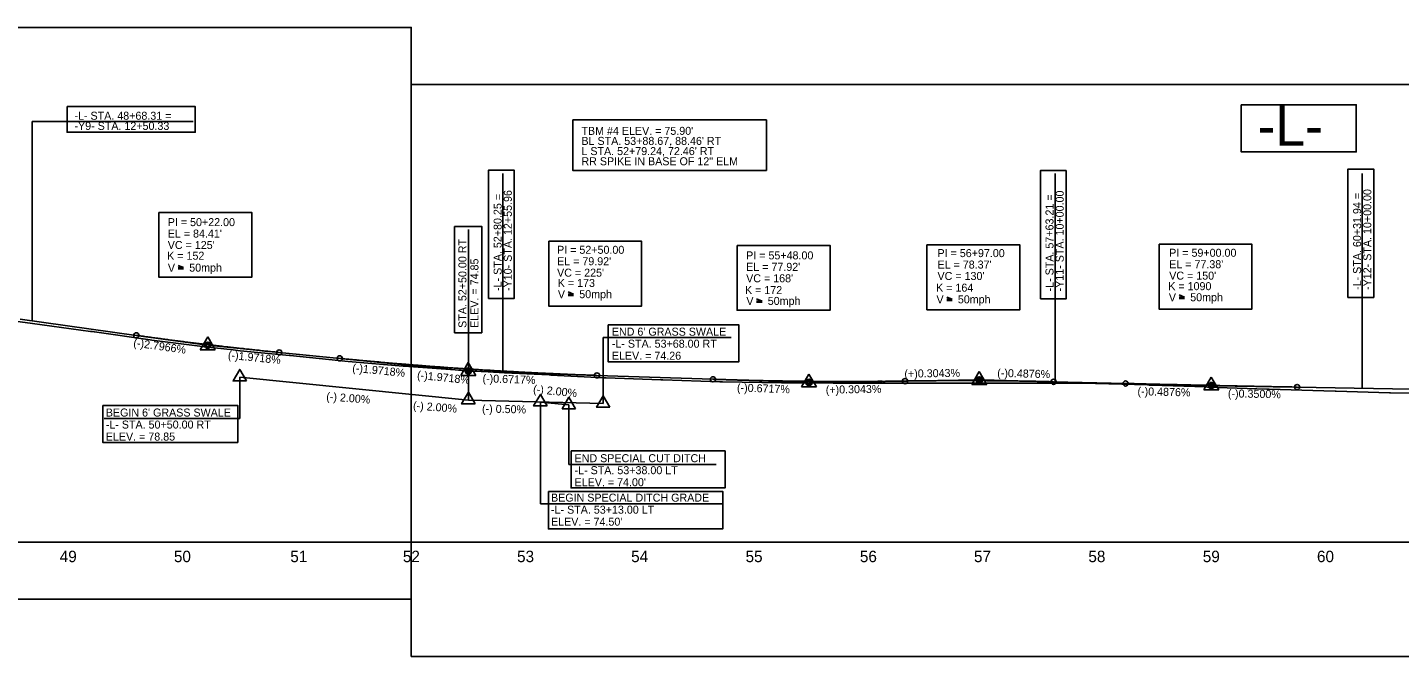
# Model space of a CAD drawing. Extents: x 2366464 to 2375718, y 801842 to 804354.
# Drawn here: x 2371182 to 2372383, y 803754 to 804304 of the extents above; entities that cross this region are included whole.
import ezdxf

# ---------------------------------------------------------------- set-up
doc = ezdxf.new("R2010")
doc.units = 0
for name, color, linetype in [('Exist Profile Cell', 7, 'Continuous'), ('Exist Vertical Profile Ground Line', 7, 'Continuous'), ('Exist Vertical Profile Horizontal Axis Label Major', 7, 'Continuous'), ('Prop Grid Mask', 7, 'Continuous'), ('Prop PFL VPI Symbol CELL', 7, 'Continuous'), ('Prop Vertical Profile Curve Label', 7, 'Continuous'), ('Prop Vertical Profile Ditch Grade Left', 7, 'Continuous'), ('Prop Vertical Profile Ditch Grade Left Label', 7, 'Continuous'), ('Prop Vertical Profile Ditch Grade Right', 7, 'Continuous'), ('Prop Vertical Profile Ditch Grade Right Label', 7, 'Continuous'), ('Prop Vertical Profile Grade', 7, 'Continuous'), ('Prop Vertical Profile Grade Label', 7, 'Continuous'), ('Prop VPI Label', 7, 'Continuous'), ('Scratch_Level_5', 7, 'Continuous'), ('Sheet Layout Profile Border Port 1', 7, 'Continuous'), ('Sheet Layout Profile Border Port 2', 7, 'Continuous')]:
    doc.layers.add(name, color=color, linetype=linetype)

# ---------------------------------------------------------------- blocks, each defined once
blk = doc.blocks.new('Profile VPI Symbol')
at = {"layer": 'Prop PFL VPI Symbol CELL'}
for p, q in [((-0.001, 0.147), (-0.13, -0.077)), ((-0.001, 0.147), (0.129, -0.077)), ((-0.13, -0.077), (0.129, -0.077))]:
    blk.add_line(p, q, dxfattribs=at)
for radius in [0.035, 0.024]:
    blk.add_circle((-0.001, -0.003), radius, dxfattribs=at)

msp = doc.modelspace()

# ---------------------------------------------------------------- linework, layer by layer
at = {"layer": 'Exist Profile Cell'}
msp.add_line((2367318, 803854), (2374481.8, 803854), dxfattribs=at)
at = {"layer": 'Exist Vertical Profile Ground Line'}
for points in [[(2371156.1, 804049.1), (2371186.8, 804045.1)], [(2371186.8, 804045.1), (2371237.4, 804038.3), (2371239.2, 804038.1), (2371240.9, 804037.8), (2371289.5, 804030.8), (2371291.1, 804030.6), (2371340.1, 804024.6), (2371340.4, 804024.5), (2371362.1, 804022), (2371368.4, 804021.4), (2371411.6, 804017.2), (2371412, 804017.2), (2371462.9, 804012), (2371511, 804007.8), (2371511.9, 804007.8), (2371560.5, 804004.3), (2371561, 804004.3), (2371599.7, 804001.9), (2371638.6, 804000.2), (2371640, 804000.1), (2371686.8, 803997.7), (2371688.6, 803997.7), (2371736.4, 803995.8), (2371738.1, 803995.8), (2371788, 803994.2), (2371789.1, 803994.2), (2371790.2, 803994.2), (2371842, 803993.3), (2371887, 803992.9), (2371887.5, 803992.9), (2371888, 803992.9), (2371914.4, 803992.9), (2371922.5, 803992.9), (2371930.6, 803992.9), (2371935.2, 803992.9), (2371935.7, 803992.9), (2371938.6, 803992.9), (2371946.7, 803992.9), (2371954.8, 803993), (2371962.8, 803993), (2371970.9, 803993), (2371979, 803993), (2371981.1, 803993), (2371987.8, 803993), (2371996.6, 803993), (2372005.4, 803993), (2372014.2, 803993), (2372023, 803993), (2372027.2, 803993), (2372028.8, 803993), (2372031.9, 803993), (2372040.7, 803993), (2372079.6, 803993), (2372080.2, 803993), (2372080.7, 803993), (2372116.5, 803992.8), (2372117, 803992.7), (2372162.2, 803991.4), (2372163.7, 803991.3), (2372165.4, 803991.3), (2372213.1, 803989.7), (2372214.7, 803989.6), (2372266.6, 803987.8), (2372268.5, 803987.8), (2372316.3, 803986.3), (2372326.4, 803986), (2372327.1, 803985.9), (2372373.9, 803984.6), (2372374.8, 803984.6), (2372426.7, 803983.6)]]:
    msp.add_lwpolyline(points, dxfattribs=at)
at = {"layer": 'Prop Grid Mask'}
for points in [[(2371216.9, 804234.8), (2371329, 804234.8), (2371329, 804212.3), (2371216.9, 804212.3)], [(2372244.1, 804236.4), (2372344.8, 804236.4), (2372344.8, 804195.1), (2372244.1, 804195.1)], [(2371659.3, 804223.2), (2371828.8, 804223.2), (2371828.8, 804179), (2371659.3, 804179)], [(2371585.6, 804067.1), (2371585.6, 804179.2), (2371608.1, 804179.2), (2371608.1, 804067.1)], [(2372068.4, 804066.7), (2372068.4, 804178.8), (2372090.9, 804178.8), (2372090.9, 804066.7)], [(2372337.4, 804068), (2372337.4, 804180.1), (2372360, 804180.1), (2372360, 804068)], [(2371297.2, 804142.3), (2371378.5, 804142.3), (2371378.5, 804085.6), (2371297.2, 804085.6)], [(2371556, 804130.1), (2371579.7, 804130.1), (2371579.7, 804037.1), (2371556, 804037.1)], [(2371638.3, 804117.1), (2371719.6, 804117.1), (2371719.6, 804060.4), (2371638.3, 804060.4)], [(2371803.1, 804113.4), (2371884.4, 804113.4), (2371884.4, 804056.7), (2371803.1, 804056.7)], [(2371969.2, 804113.9), (2372050.5, 804113.9), (2372050.5, 804057.2), (2371969.2, 804057.2)], [(2372172.2, 804114.5), (2372253.5, 804114.5), (2372253.5, 804057.8), (2372172.2, 804057.8)], [(2371690.2, 804043.9), (2371804.7, 804043.9), (2371804.7, 804011.7), (2371690.2, 804011.7)], [(2371248.2, 803973.5), (2371366.3, 803973.5), (2371366.3, 803941.2), (2371248.2, 803941.2)], [(2371657.8, 803933.8), (2371792.6, 803933.8), (2371792.6, 803901.4), (2371657.8, 803901.4)], [(2371638, 803898.3), (2371790.5, 803898.3), (2371790.5, 803865.5), (2371638, 803865.5)]]:
    msp.add_lwpolyline(points, close=True, dxfattribs=at)
at = {"layer": 'Prop Vertical Profile Curve Label'}
for p, q in [((2371314, 804094), (2371318.8, 804094)), ((2371314, 804092.9), (2371318.8, 804092.9)), ((2371318.8, 804094), (2371314.1, 804096)), ((2371655.3, 804070.7), (2371660, 804070.7)), ((2371655.3, 804069.7), (2371660, 804069.7)), ((2371660, 804070.7), (2371655.4, 804072.7)), ((2371820.1, 804064.8), (2371824.9, 804064.8)), ((2371820.1, 804063.8), (2371824.9, 804063.8)), ((2371824.9, 804064.8), (2371820.2, 804066.8)), ((2371986.5, 804066.3), (2371991.2, 804066.3)), ((2371986.5, 804065.2), (2371991.2, 804065.2)), ((2371991.2, 804066.3), (2371986.6, 804068.3)), ((2372189.7, 804068.1), (2372194.5, 804068.1)), ((2372189.7, 804067), (2372194.5, 804067)), ((2372194.5, 804068.1), (2372189.8, 804070.1))]:
    msp.add_line(p, q, dxfattribs=at)
for centre in [(2371277.5, 804034.8), (2371402.5, 804019.9), (2371455.5, 804014.7), (2371680.5, 803999.8), (2371782, 803996.4), (2371950, 803994.8), (2371950, 803994.8), (2372080, 803994.2), (2372143, 803992.7), (2372293, 803989.6)]:
    msp.add_circle(centre, 2.25, dxfattribs=at)
at = {"layer": 'Prop Vertical Profile Ditch Grade Left'}
msp.add_line((2371631, 803976.5), (2371656, 803974), dxfattribs=at)
at = {"layer": 'Prop Vertical Profile Ditch Grade Left Label'}
for p, q in [((2371631, 803887.5), (2371631, 803976.5)), ((2371656, 803922), (2371656, 803974)), ((2371784.8, 803922), (2371656, 803922)), ((2371789.8, 803887.5), (2371631, 803887.5))]:
    msp.add_line(p, q, dxfattribs=at)
for points in [[(2371636.8, 803973.1), (2371631, 803983.2), (2371625.1, 803973.1)], [(2371661.8, 803970.6), (2371656, 803980.7), (2371650.1, 803970.6)]]:
    msp.add_lwpolyline(points, close=True, dxfattribs=at)
at = {"layer": 'Prop Vertical Profile Ditch Grade Right'}
for p, q in [((2371368, 803998.2), (2371568, 803978.2)), ((2371568, 803978.2), (2371686, 803975.3))]:
    msp.add_line(p, q, dxfattribs=at)
at = {"layer": 'Prop Vertical Profile Ditch Grade Right Label'}
for p, q in [((2371568, 804127.2), (2371568, 804035.9)), ((2371568, 804035.9), (2371568, 803978.2)), ((2371686, 804032.9), (2371686, 803975.3)), ((2371797.8, 804032.9), (2371686, 804032.9)), ((2371368, 803962), (2371368, 803998.2)), ((2371368, 803962), (2371249.5, 803962))]:
    msp.add_line(p, q, dxfattribs=at)
for points in [[(2371373.8, 803994.9), (2371368, 804005), (2371362.1, 803994.9)], [(2371573.8, 803974.9), (2371568, 803985), (2371562.1, 803974.9)], [(2371691.8, 803971.9), (2371686, 803982), (2371680.1, 803971.9)]]:
    msp.add_lwpolyline(points, close=True, dxfattribs=at)
at = {"layer": 'Prop Vertical Profile Grade'}
for p, q in [((2371176, 804049), (2371277.5, 804034.8)), ((2371402.5, 804019.9), (2371455.5, 804014.7)), ((2371680.5, 803999.8), (2371782, 803996.4)), ((2372080, 803994.2), (2372143, 803992.7)), ((2372293, 803989.6), (2372808, 803980.6))]:
    msp.add_line(p, q, dxfattribs=at)
for points in [[(2371277.5, 804034.8), (2371280, 804034.4), (2371282.5, 804034.1), (2371285, 804033.8), (2371287.5, 804033.4), (2371290, 804033.1), (2371292.5, 804032.7), (2371295, 804032.4), (2371297.5, 804032.1), (2371300, 804031.7), (2371302.5, 804031.4), (2371305, 804031.1), (2371307.5, 804030.7), (2371310, 804030.4), (2371312.5, 804030.1), (2371315, 804029.8), (2371317.5, 804029.5), (2371320, 804029.1), (2371322.5, 804028.8), (2371325, 804028.5), (2371327.5, 804028.2), (2371330, 804027.9), (2371332.5, 804027.6), (2371335, 804027.3), (2371337.5, 804027), (2371340, 804026.7), (2371342.5, 804026.4), (2371345, 804026.1), (2371347.5, 804025.8), (2371350, 804025.5), (2371352.5, 804025.2), (2371355, 804024.9), (2371357.5, 804024.7), (2371360, 804024.4), (2371362.5, 804024.1), (2371365, 804023.8), (2371367.5, 804023.5), (2371370, 804023.3), (2371372.5, 804023), (2371375, 804022.7), (2371377.5, 804022.5), (2371380, 804022.2), (2371382.5, 804021.9), (2371385, 804021.7), (2371387.5, 804021.4), (2371390, 804021.1), (2371392.5, 804020.9), (2371395, 804020.6), (2371397.5, 804020.4), (2371400, 804020.1), (2371402.5, 804019.9)], [(2371455.5, 804014.7), (2371460, 804014.2), (2371464.5, 804013.8), (2371469, 804013.4), (2371473.5, 804012.9), (2371478, 804012.5), (2371482.5, 804012.1), (2371487, 804011.7), (2371491.5, 804011.3), (2371496, 804010.9), (2371500.5, 804010.5), (2371505, 804010.1), (2371509.5, 804009.8), (2371514, 804009.4), (2371518.5, 804009), (2371523, 804008.7), (2371527.5, 804008.3), (2371532, 804008), (2371536.5, 804007.6), (2371541, 804007.3), (2371545.5, 804007), (2371550, 804006.6), (2371554.5, 804006.3), (2371559, 804006), (2371563.5, 804005.7), (2371568, 804005.4), (2371572.5, 804005.1), (2371577, 804004.8), (2371581.5, 804004.5), (2371586, 804004.3), (2371590.5, 804004), (2371595, 804003.7), (2371599.5, 804003.5), (2371604, 804003.2), (2371608.5, 804003), (2371613, 804002.7), (2371617.5, 804002.5), (2371622, 804002.3), (2371626.5, 804002), (2371631, 804001.8), (2371635.5, 804001.6), (2371640, 804001.4), (2371644.5, 804001.2), (2371649, 804001), (2371653.5, 804000.8), (2371658, 804000.6), (2371662.5, 804000.4), (2371667, 804000.3), (2371671.5, 804000.1), (2371676, 803999.9), (2371680.5, 803999.8)], [(2371782, 803996.4), (2371785.3, 803996.3), (2371788.7, 803996.2), (2371792.1, 803996.1), (2371795.4, 803996), (2371798.8, 803995.9), (2371802.1, 803995.8), (2371805.5, 803995.7), (2371808.9, 803995.6), (2371812.2, 803995.5), (2371815.6, 803995.4), (2371818.9, 803995.3), (2371822.3, 803995.3), (2371825.7, 803995.2), (2371829, 803995.1), (2371832.4, 803995.1), (2371835.7, 803995), (2371839.1, 803994.9), (2371842.5, 803994.9), (2371845.8, 803994.8), (2371849.2, 803994.8), (2371852.5, 803994.7), (2371855.9, 803994.7), (2371859.3, 803994.7), (2371862.6, 803994.6), (2371866, 803994.6), (2371869.3, 803994.6), (2371872.7, 803994.5), (2371876.1, 803994.5), (2371879.4, 803994.5), (2371882.8, 803994.5), (2371886.1, 803994.5), (2371889.5, 803994.5), (2371892.9, 803994.4), (2371896.2, 803994.4), (2371899.6, 803994.4), (2371902.9, 803994.4), (2371906.3, 803994.5), (2371909.7, 803994.5), (2371913, 803994.5), (2371916.4, 803994.5), (2371919.7, 803994.5), (2371923.1, 803994.5), (2371926.5, 803994.6), (2371929.8, 803994.6), (2371933.2, 803994.6), (2371936.5, 803994.7), (2371939.9, 803994.7), (2371943.3, 803994.7), (2371946.6, 803994.8), (2371950, 803994.8)], [(2371950, 803994.8), (2371952.6, 803994.9), (2371955.2, 803994.9), (2371957.8, 803995), (2371960.4, 803995), (2371963, 803995), (2371965.6, 803995), (2371968.2, 803995.1), (2371970.8, 803995.1), (2371973.4, 803995.1), (2371976, 803995.1), (2371978.6, 803995.2), (2371981.2, 803995.2), (2371983.8, 803995.2), (2371986.4, 803995.2), (2371989, 803995.2), (2371991.6, 803995.2), (2371994.2, 803995.2), (2371996.8, 803995.2), (2371999.4, 803995.2), (2372002, 803995.2), (2372004.6, 803995.2), (2372007.2, 803995.2), (2372009.8, 803995.2), (2372012.4, 803995.2), (2372015, 803995.2), (2372017.6, 803995.2), (2372020.2, 803995.2), (2372022.8, 803995.1), (2372025.4, 803995.1), (2372028, 803995.1), (2372030.6, 803995.1), (2372033.2, 803995.1), (2372035.8, 803995), (2372038.4, 803995), (2372041, 803995), (2372043.6, 803994.9), (2372046.2, 803994.9), (2372048.8, 803994.9), (2372051.4, 803994.8), (2372054, 803994.8), (2372056.6, 803994.7), (2372059.2, 803994.7), (2372061.8, 803994.6), (2372064.4, 803994.6), (2372067, 803994.5), (2372069.6, 803994.5), (2372072.2, 803994.4), (2372074.8, 803994.4), (2372077.4, 803994.3), (2372080, 803994.2)], [(2372143, 803992.7), (2372146, 803992.6), (2372149, 803992.6), (2372152, 803992.5), (2372155, 803992.4), (2372158, 803992.4), (2372161, 803992.3), (2372164, 803992.2), (2372167, 803992.1), (2372170, 803992.1), (2372173, 803992), (2372176, 803991.9), (2372179, 803991.9), (2372182, 803991.8), (2372185, 803991.7), (2372188, 803991.7), (2372191, 803991.6), (2372194, 803991.5), (2372197, 803991.5), (2372200, 803991.4), (2372203, 803991.3), (2372206, 803991.3), (2372209, 803991.2), (2372212, 803991.1), (2372215, 803991.1), (2372218, 803991), (2372221, 803990.9), (2372224, 803990.9), (2372227, 803990.8), (2372230, 803990.8), (2372233, 803990.7), (2372236, 803990.6), (2372239, 803990.6), (2372242, 803990.5), (2372245, 803990.5), (2372248, 803990.4), (2372251, 803990.3), (2372254, 803990.3), (2372257, 803990.2), (2372260, 803990.2), (2372263, 803990.1), (2372266, 803990.1), (2372269, 803990), (2372272, 803989.9), (2372275, 803989.9), (2372278, 803989.8), (2372281, 803989.8), (2372284, 803989.7), (2372287, 803989.7), (2372290, 803989.6), (2372293, 803989.6)]]:
    msp.add_spline(points, degree=3, dxfattribs=at)
at = {"layer": 'Prop VPI Label'}
for p, q in [((2371186.3, 804047.5), (2371186.3, 804221.9)), ((2371186.3, 804221.9), (2371327.2, 804221.9)), ((2371598.2, 804003.5), (2371598.2, 804176.4)), ((2372081.2, 803994.2), (2372081.2, 804176.4)), ((2372349.9, 803988.6), (2372349.9, 804176.4)), ((2371277.5, 804034.8), (2371337.3, 804026.4)), ((2371402.5, 804019.9), (2371342.7, 804025.8)), ((2371455.5, 804014.7), (2371565.2, 804003.8)), ((2371680.5, 803999.8), (2371570.7, 804003.5)), ((2371782, 803996.4), (2371863.2, 803993.7)), ((2371950, 803994.8), (2371868.7, 803993.6)), ((2371950, 803994.8), (2372012.2, 803995.8)), ((2372080, 803994.2), (2372017.7, 803995.8)), ((2372143, 803992.7), (2372215.2, 803990.9)), ((2372293, 803989.6), (2372220.7, 803990.8))]:
    msp.add_line(p, q, dxfattribs=at)
for centre in [(2371340, 804026.1), (2371568, 804003.6), (2371866, 803993.6), (2372015, 803995.8), (2372218, 803990.9)]:
    msp.add_circle(centre, 2.75, dxfattribs=at)
at = {"layer": 'Scratch_Level_5'}
for p, q in [((2371318, 804029.3), (2371318, 804029.3)), ((2372018, 803994.2), (2372018, 803994.2)), ((2372081.2, 803993.8), (2372081.2, 803993.8)), ((2372218, 803990.9), (2372218, 803990.9))]:
    msp.add_line(p, q, dxfattribs=at)
at = {"layer": 'Sheet Layout Profile Border Port 1'}
msp.add_lwpolyline([(2370118, 803804), (2371518, 803804), (2371518, 804304), (2370118, 804304)], close=True, dxfattribs=at)
at = {"layer": 'Sheet Layout Profile Border Port 2'}
msp.add_lwpolyline([(2371518, 803754), (2372918, 803754), (2372918, 804254), (2371518, 804254)], close=True, dxfattribs=at)

# ---------------------------------------------------------------- block references
at = {"layer": 'Prop Grid Mask', "xscale": 50, "yscale": 50}
for p in [(2371340, 804026.1), (2371568, 804003.6), (2371866, 803993.6), (2372015, 803995.8), (2372218, 803990.9)]:
    msp.add_blockref('Profile VPI Symbol', p, dxfattribs=at)

# ---------------------------------------------------------------- texts
at = {"layer": 'Exist Vertical Profile Horizontal Axis Label Major'}
for s, p in [('49', (2371210.5, 803836.5)), ('50', (2371310.4, 803836.5)), ('51', (2371412.2, 803836.5)), ('52', (2371510.7, 803836.5)), ('53', (2371610.6, 803836.5)), ('54', (2371710.4, 803836.5)), ('55', (2371810.5, 803836.5)), ('56', (2371910.5, 803836.5)), ('57', (2372010.3, 803836.5)), ('58', (2372110.4, 803836.5)), ('59', (2372210.5, 803836.5)), ('60', (2372310.4, 803836.5))]:
    msp.add_text(s, height=10, dxfattribs=at).set_placement(p)
at = {"layer": 'Prop Vertical Profile Curve Label'}
for s, rotation, p in [('-L- STA. 48+68.31 = ', 360, (2371223.4, 804223.3)), ('-Y9- STA. 12+50.33', 360, (2371223.4, 804214.4)), ('-L- STA. 52+80.25 = ', 90, (2371597.1, 804073.6)), ('-Y10- STA. 12+55.96', 90, (2371606, 804073.6)), ('-L- STA. 57+63.21 = ', 90, (2372079.9, 804073.2)), ('-Y11- STA. 10+00.00', 90, (2372088.8, 804073.2)), ('-L- STA. 60+31.94 = ', 90, (2372349, 804074.5)), ('-Y12- STA. 10+00.00', 90, (2372357.9, 804074.5))]:
    msp.add_text(s, height=7, rotation=rotation, dxfattribs=at).set_placement(p)
for s, p in [("VC = 125'", (2371305, 804110.3)), ('V', (2371305.1, 804090.4)), ('K = 152', (2371304.5, 804100.9)), ('50mph', (2371323.8, 804090.5)), ("VC = 225'", (2371645.6, 804086.1)), ("VC = 168'", (2371811, 804081.2)), ("VC = 130'", (2371978.4, 804083.2)), ("VC = 150'", (2372181.1, 804083.5)), ('V', (2371646.3, 804067.2)), ('K = 173', (2371646.2, 804077.1)), ('50mph', (2371665, 804067.3)), ('K = 172', (2371810, 804070.9)), ('K = 164', (2371977.2, 804073)), ('K = 1090', (2372180.3, 804074.3)), ('V', (2371811.2, 804061.3)), ('50mph', (2371829.9, 804061.4)), ('V', (2371977.5, 804062.7)), ('50mph', (2371996.2, 804062.8)), ('V', (2372180.8, 804064.5)), ('50mph', (2372199.5, 804064.6))]:
    msp.add_text(s, height=7, dxfattribs=at).set_placement(p)
at = {"layer": 'Prop Vertical Profile Ditch Grade Left Label'}
msp.add_text('(-) 2.00%', height=7, rotation=354.2894, dxfattribs=at).set_placement((2371624.4, 803984.5))
for s, p in [('END SPECIAL CUT DITCH ', (2371660.9, 803923.9)), ('-L- STA. 53+38.00 LT', (2371660.9, 803913.4)), ("ELEV. = 74.00'", (2371660.9, 803902.9)), ('BEGIN SPECIAL DITCH GRADE', (2371640.3, 803889.4)), ('-L- STA. 53+13.00 LT', (2371640.3, 803878.9)), ("ELEV. = 74.50'", (2371640.3, 803868.4))]:
    msp.add_text(s, height=7, dxfattribs=at).set_placement(p)
at = {"layer": 'Prop Vertical Profile Ditch Grade Right Label'}
for s, rotation, p in [('STA. 52+50.00 RT', 90, (2371566.3, 804041.3)), ('ELEV. = 74.85', 90, (2371576.8, 804041.3)), ('(-) 2.00%', 355.6629, (2371443.5, 803978)), ('(-) 2.00%', 355.6629, (2371519.4, 803970.1)), ('(-) 0.50%', 358.7583, (2371579.9, 803967.3))]:
    msp.add_text(s, height=7, rotation=rotation, dxfattribs=at).set_placement(p)
for s, p in [("END 6' GRASS SWALE", (2371693.5, 804034.5)), ('-L- STA. 53+68.00 RT', (2371693.5, 804024)), ('ELEV. = 74.26', (2371693.5, 804013.5)), ("BEGIN 6' GRASS SWALE", (2371250.8, 803963.8)), ('-L- STA. 50+50.00 RT', (2371250.8, 803953.3)), ('ELEV. = 78.85', (2371250.8, 803942.8))]:
    msp.add_text(s, height=7, dxfattribs=at).set_placement(p)
at = {"layer": 'Prop Vertical Profile Grade Label'}
for s, rotation, p in [('(-)2.7966%', 352.0399, (2371274.6, 804025.1)), ('(-)1.9718%', 354.3694, (2371357.4, 804014.3)), ('(-)1.9718%', 354.3694, (2371466.2, 804003)), ('(-)1.9718%', 354.3694, (2371522.9, 803996.8)), ('(-)0.6717%', 358.0765, (2371580.3, 803993.8)), ('(+)0.3043%', 0.8717, (2371949.5, 803997.8)), ('(-)0.4876%', 358.6034, (2372030.6, 803998.5)), ('(-)0.6717%', 358.0765, (2371802.9, 803985.7)), ('(+)0.3043%', 0.8717, (2371880.7, 803983.8)), ('(-)0.4876%', 358.6034, (2372153.3, 803982.5)), ('(-)0.3500%', 358.9974, (2372232.4, 803980.6))]:
    msp.add_text(s, height=7, rotation=rotation, dxfattribs=at).set_placement(p)
at = {"layer": 'Prop VPI Label'}
for s, height, p in [('-L-', 35, (2372258.4, 804200.6)), ("TBM #4 ELEV. = 75.90'", 7, (2371666.9, 804210.1)), ("BL STA. 53+88.67, 88.46' RT", 7, (2371666.9, 804201.3)), ("L STA. 52+79.24, 72.46' RT", 7, (2371666.9, 804192.4)), ('RR SPIKE IN BASE OF 12" ELM', 7, (2371666.9, 804183.5)), ('PI = 50+22.00', 7, (2371305, 804130.3)), ("EL = 84.41'", 7, (2371305, 804120.3)), ('PI = 52+50.00', 7, (2371645.6, 804106.1)), ('PI = 56+97.00', 7, (2371978.4, 804103.2)), ('PI = 59+00.00', 7, (2372181.1, 804103.5)), ("EL = 79.92'", 7, (2371645.6, 804096.1)), ('PI = 55+48.00', 7, (2371811, 804101.2)), ("EL = 77.92'", 7, (2371811, 804091.2)), ("EL = 78.37'", 7, (2371978.4, 804093.2)), ("EL = 77.38'", 7, (2372181.1, 804093.5))]:
    msp.add_text(s, height=height, dxfattribs=at).set_placement(p)

doc.saveas('drawing.dxf')
